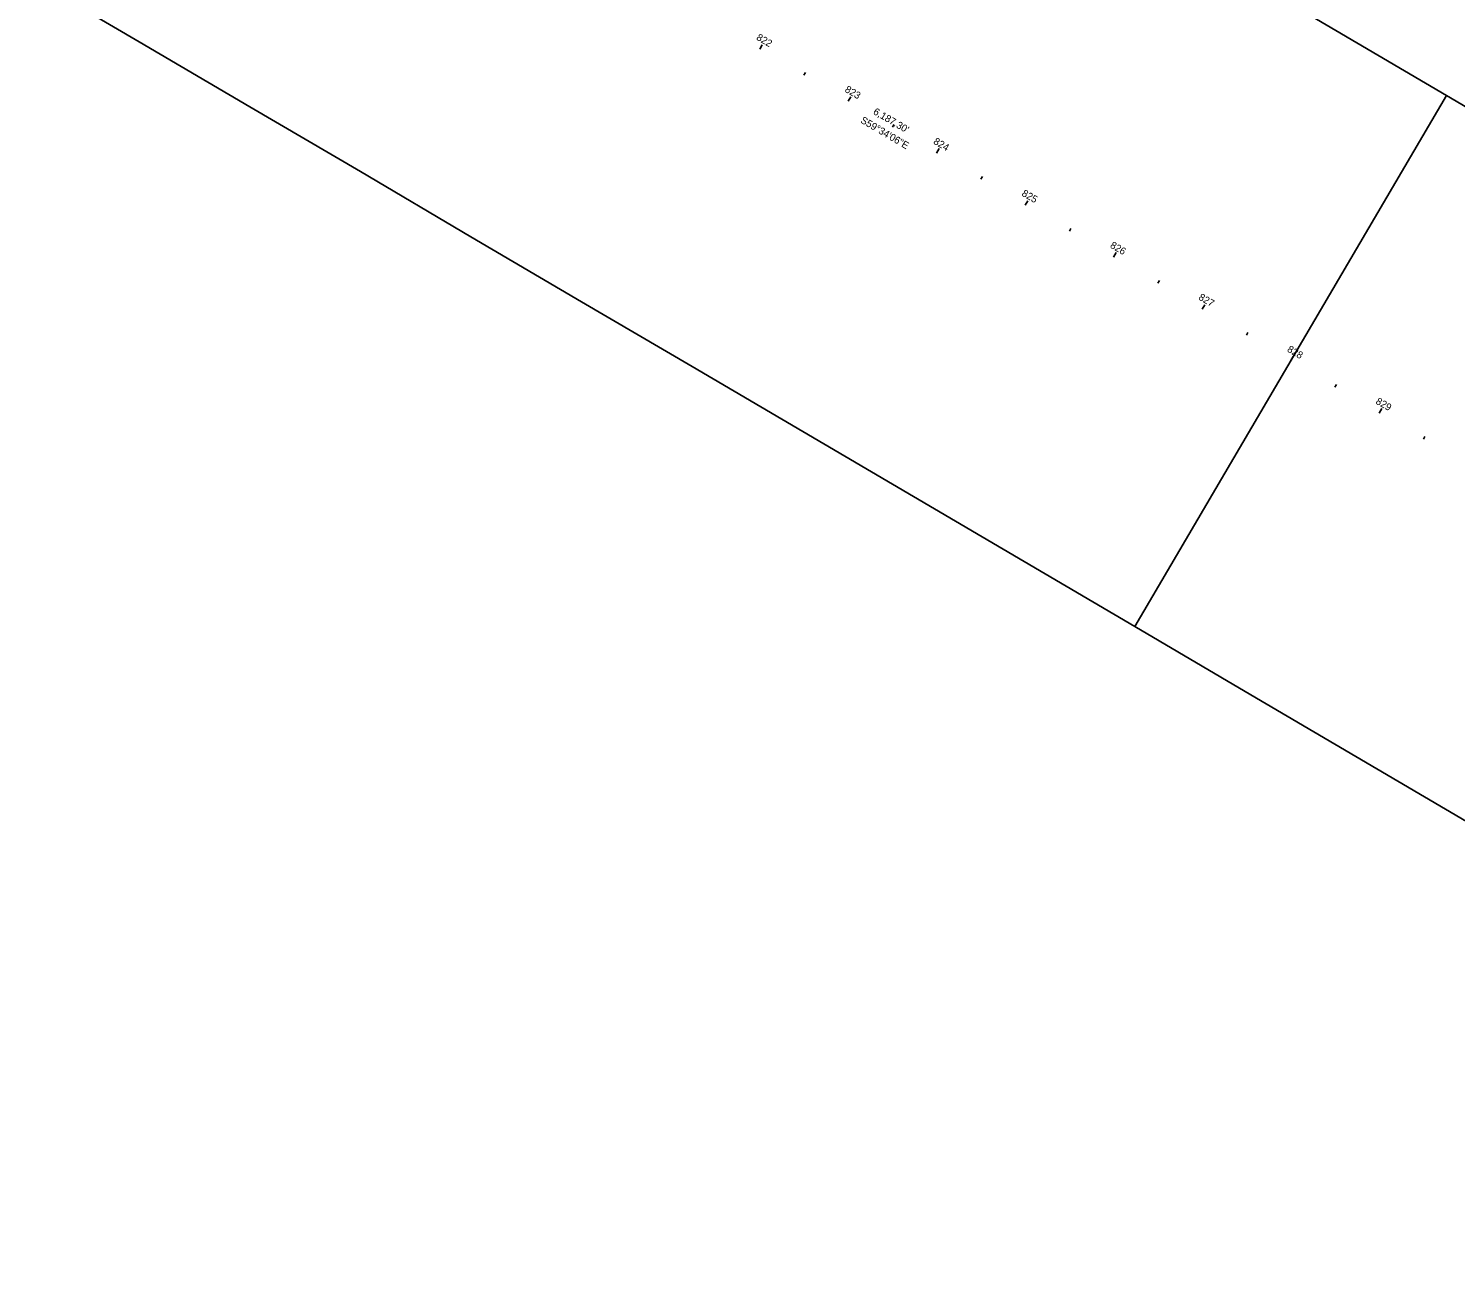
# Model space of a CAD drawing. Extents: x 75725 to 90554, y 518585 to 527848.
# Drawn here: x 83746 to 85137, y 523229 to 524445 of the extents above; entities that cross this region are included whole.
import ezdxf

# ---------------------------------------------------------------- set-up
doc = ezdxf.new("R2010")
doc.units = 0
for name, color, linetype in [('GE_P_Alignment_100_Bearings', 7, 'Continuous'), ('GE_P_Alignment_100_Distances', 7, 'Continuous'), ('GE_P_Alignment_100_Stations', 7, 'Continuous'), ('SH_Named_Boundary', 7, 'Continuous')]:
    doc.layers.add(name, color=color, linetype=linetype)

msp = doc.modelspace()

# ---------------------------------------------------------------- linework, layer by layer
at = {"layer": 'GE_P_Alignment_100_Stations'}
for p, q in [((84458.6, 524424.7), (84461.1, 524429.1)), ((84501.7, 524399.4), (84503.2, 524402)), ((84544.8, 524374.1), (84547.4, 524378.4)), ((84587.9, 524348.8), (84589.4, 524351.4)), ((84631, 524323.4), (84633.6, 524327.8)), ((84674.2, 524298.1), (84675.7, 524300.7)), ((84717.3, 524272.8), (84719.8, 524277.1)), ((84760.4, 524247.5), (84761.9, 524250.1)), ((84803.5, 524222.1), (84806, 524226.5)), ((84846.6, 524196.8), (84848.1, 524199.4)), ((84889.7, 524171.5), (84892.2, 524175.8)), ((84932.8, 524146.2), (84934.3, 524148.8)), ((84975.9, 524120.8), (84978.5, 524125.2)), ((85019, 524095.5), (85020.6, 524098.1)), ((85062.2, 524070.2), (85064.7, 524074.5)), ((85105.3, 524044.9), (85106.8, 524047.5))]:
    msp.add_line(p, q, dxfattribs=at)
at = {"layer": 'SH_Named_Boundary'}
for points in [[(84050.1, 525012.6), (83746.2, 524495.3), (83854, 524432), (83961.8, 524368.7), (84069.6, 524305.4), (84177.3, 524242), (84285.1, 524178.7), (84392.9, 524115.4), (84500.7, 524052.1), (84608.5, 523988.8), (84716.2, 523925.5), (84824, 523862.2), (85127.9, 524379.5), (85020.1, 524442.8), (84912.4, 524506.1), (84804.6, 524569.4), (84696.8, 524632.8), (84589, 524696.1), (84481.2, 524759.4), (84373.5, 524822.7), (84265.7, 524886), (84157.9, 524949.3)], [(85127.9, 524379.5), (84824, 523862.2), (84931.8, 523798.8), (85039.6, 523735.5), (85147.4, 523672.2), (85255.1, 523608.9), (85362.9, 523545.6), (85470.7, 523482.3), (85578.5, 523419), (85686.2, 523355.6), (85794, 523292.3), (85901.8, 523229), (86205.7, 523746.4), (86097.9, 523809.7), (85990.2, 523873), (85882.4, 523936.3), (85774.6, 523999.6), (85666.8, 524062.9), (85559, 524126.2), (85451.3, 524189.6), (85343.5, 524252.9), (85235.7, 524316.2)]]:
    msp.add_lwpolyline(points, close=True, dxfattribs=at)

# ---------------------------------------------------------------- texts
at = {"layer": 'GE_P_Alignment_100_Bearings'}
msp.add_text('S59°34\'06"E', height=7, rotation=329.5684, dxfattribs=at).set_placement((84556.1, 524353.6))
at = {"layer": 'GE_P_Alignment_100_Distances'}
msp.add_text("6,187.30'", height=7, rotation=329.5684, dxfattribs=at).set_placement((84568.5, 524362))
at = {"layer": 'GE_P_Alignment_100_Stations'}
for s, p in [('822', (84454.7, 524434.3)), ('823', (84540.9, 524383.6)), ('824', (84627.2, 524333)), ('825', (84713.3, 524282.4)), ('826', (84799.4, 524231.8)), ('827', (84885.5, 524181.2)), ('828', (84971.9, 524130.5)), ('829', (85058.2, 524079.8))]:
    msp.add_text(s, height=7, rotation=329.5684, dxfattribs=at).set_placement(p)

doc.saveas('drawing.dxf')
